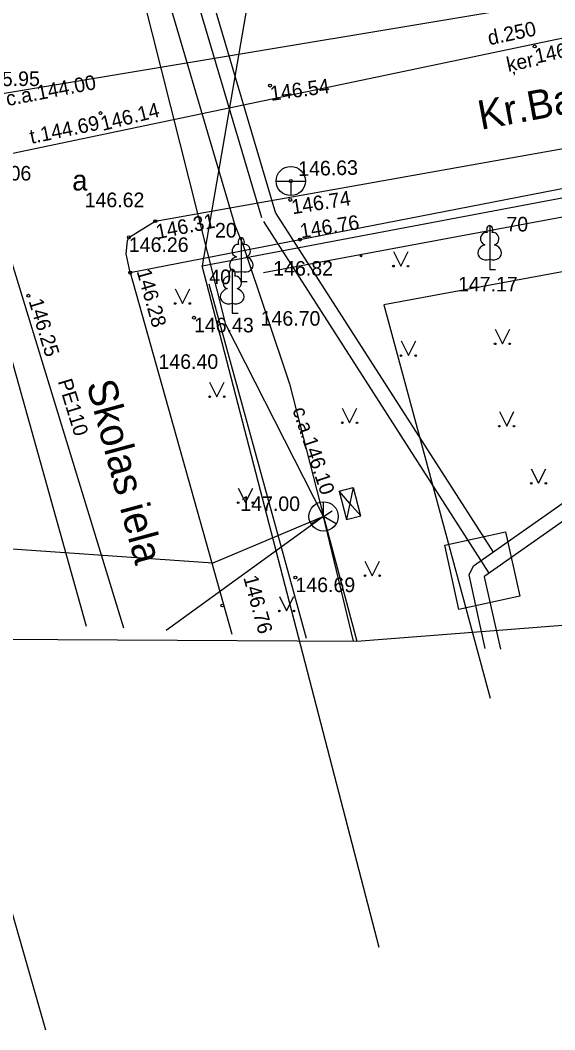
# Model space of a CAD drawing. Extents: x 728492 to 729038, y 272968 to 273171.
# Drawn here: x 728538.74 to 728557.05, y 273019.88 to 273054.47 of the extents above; entities that cross this region are included whole.
import ezdxf

# ---------------------------------------------------------------- set-up
doc = ezdxf.new("R2010")
doc.units = 0
for name, color, linetype in [('APGR_SARK_####_####_#', 7, 'Continuous'), ('CELI_CAPM_####_####_#', 7, 'Continuous'), ('CELI_CMAL_####_####_#', 7, 'Continuous'), ('CELI_CSEG_####_TKST_#', 7, 'Continuous'), ('CELI_IELA_####_TKST_#', 7, 'Continuous'), ('RAMI_UZMR_####_####_#', 7, 'Continuous'), ('RELJ_AATZ_####_TKST_#', 7, 'Continuous'), ('RELJ_ELEM_####_####_#', 7, 'Continuous'), ('ROBZ_UZMR_####_####_#', 7, 'Continuous'), ('SAKK_DETV_####_####_#', 7, 'Continuous'), ('SAKK_ELEM_####_####_#', 7, 'Continuous'), ('SAKK_ELEM_####_TKST_#', 7, 'Continuous'), ('SAKK_KKAN_####_####_#', 7, 'Continuous'), ('SAKK_KKAN_####_TKST_#', 7, 'Continuous'), ('SAKT_ELEM_####_####_#', 7, 'Continuous'), ('SAKT_VADP_KABE_####_#', 7, 'Continuous'), ('SILT_ELEM_####_####_#', 7, 'Continuous'), ('SILT_ELEM_####_TKST_#', 7, 'Continuous'), ('SILT_VADP_UDEN_####_#', 7, 'Continuous'), ('SILT_VADP_UDEN_TKAM_#', 7, 'Continuous'), ('SKAN_ELEM_####_####_#', 7, 'Continuous'), ('SKAN_VADP_PAST_####_#', 7, 'Continuous'), ('SKAN_VADP_PAST_TKST_#', 7, 'Continuous'), ('TERT_DIAM_####_TKST_#', 7, 'Continuous'), ('TERT_DZOG_####_####_#', 7, 'Continuous'), ('TERT_ELEM_####_####_#', 7, 'Continuous'), ('UDTK_ELEM_####_TKST_#', 7, 'Continuous'), ('UDTK_VADP_UDEN_####_#', 7, 'Continuous'), ('UDTK_VADP_UDEN_TKST_#', 7, 'Continuous')]:
    doc.layers.add(name, color=color, linetype=linetype)

msp = doc.modelspace()

# ---------------------------------------------------------------- linework, layer by layer
at = {"layer": 'APGR_SARK_####_####_#'}
for points in [[(728661.295, 273065.109), (728551.197, 273044.726)], [(728551.197, 273044.726), (728554.836, 273031.249)]]:
    msp.add_lwpolyline(points, dxfattribs=at)
at = {"layer": 'CELI_CAPM_####_####_#'}
msp.add_line((728542.512, 273045.823), (728545.993, 273033.435), dxfattribs=at)
for points in [[(728543.367, 273047.586), (728557.526, 273050.114), (728572.173, 273053.046)], [(728542.512, 273045.823), (728542.372, 273046.465), (728542.421, 273046.914), (728542.463, 273047.032), (728543.367, 273047.586)]]:
    msp.add_lwpolyline(points, dxfattribs=at)
at = {"layer": 'CELI_CMAL_####_####_#'}
msp.add_lwpolyline([(728542.512, 273045.823), (728558.294, 273048.902), (728568.705, 273050.681)], dxfattribs=at)
at = {"layer": 'RAMI_UZMR_####_####_#'}
msp.add_lwpolyline([(728545.121, 273067.256), (728525.538, 273066.106), (728511.145, 273059.016), (728527.731, 273033.328), (728550.271, 273033.197), (728572.013, 273034.886), (728580.562, 273045.27), (728653.673, 273058.931), (728671.713, 273053.291), (728688.721, 273058.407), (728702.149, 273066.922)], dxfattribs=at)
at = {"layer": 'RELJ_ELEM_####_####_#'}
for centre in [(728556.357, 273053.573), (728547.298, 273052.233), (728541.493, 273051.291), (728548.006, 273048.962), (728547.989, 273048.314), (728543.367, 273047.586), (728542.463, 273047.032), (728548.324, 273046.957), (728542.512, 273045.823), (728539.025, 273045.032), (728544.694, 273044.277), (728548.167, 273035.378), (728545.667, 273034.42)]:
    msp.add_circle(centre, 0.05, dxfattribs=at)
at = {"layer": 'ROBZ_UZMR_####_####_#'}
for p, q in [((728547.311, 273059.662), (728544.976, 273046.06)), ((728544.976, 273046.06), (728578.327, 273052.35)), ((728551.037, 273022.708), (728544.976, 273046.06)), ((728533.371, 273041.664), (728539.608, 273019.883))]:
    msp.add_line(p, q, dxfattribs=at)
at = {"layer": 'SAKK_DETV_####_####_#'}
msp.add_line((728549.129, 273037.471), (728549.42, 273037.668), dxfattribs=at)
at = {"layer": 'SAKK_ELEM_####_####_#'}
for p, q in [((728549.13, 273037.473), (728549.13, 273037.972)), ((728548.696, 273037.223), (728549.13, 273037.473)), ((728549.13, 273037.473), (728549.129, 273037.472)), ((728549.563, 273037.223), (728549.13, 273037.473))]:
    msp.add_line(p, q, dxfattribs=at)
msp.add_circle((728549.129, 273037.471), 0.5, dxfattribs=at)
at = {"layer": 'SAKK_KKAN_####_####_#'}
msp.add_lwpolyline([(728540.095, 273067.793), (728546.092, 273047.448), (728546.377, 273046.751), (728547.961, 273042.009), (728549.129, 273037.471), (728550.271, 273033.197)], dxfattribs=at)
at = {"layer": 'SAKT_ELEM_####_####_#'}
for p, q in [((728550.146, 273038.464), (728550.399, 273037.493)), ((728549.662, 273038.338), (728549.917, 273037.364))]:
    msp.add_line(p, q, dxfattribs=at)
for points in [[(728550.146, 273038.463), (728550.026, 273037.913), (728549.663, 273038.338)], [(728550.401, 273037.494), (728550.027, 273037.911), (728549.917, 273037.365)]]:
    msp.add_lwpolyline(points, close=True, dxfattribs=at)
at = {"layer": 'SAKT_VADP_KABE_####_#'}
for points in [[(728549.129, 273037.471), (728545.783, 273044.05), (728542.34, 273057.723), (728539.193, 273068.196)], [(728549.129, 273037.471), (728545.341, 273035.871), (728536.823, 273036.463), (728531.461, 273037.656), (728530.594, 273038.125), (728526.6, 273041.809), (728514.8, 273057.81)], [(728549.129, 273037.471), (728543.739, 273033.561)], [(728550.159, 273033.203), (728549.129, 273037.471)]]:
    msp.add_lwpolyline(points, dxfattribs=at)
at = {"layer": 'SILT_ELEM_####_####_#'}
for p, q in [((728547.506, 273048.962), (728548.006, 273048.962)), ((728548.006, 273048.962), (728548.506, 273048.962)), ((728548.006, 273048.962), (728548.006, 273048.462))]:
    msp.add_line(p, q, dxfattribs=at)
msp.add_circle((728548.006, 273048.962), 0.5, dxfattribs=at)
at = {"layer": 'SILT_VADP_UDEN_####_#'}
for p, q in [((728547.012, 273047.706), (728541.056, 273067.855)), ((728547.492, 273047.847), (728541.567, 273067.888))]:
    msp.add_line(p, q, dxfattribs=at)
for points in [[(728554.662, 273032.952), (728554.113, 273035.473), (728554.267, 273035.774), (728581.419, 273054.878), (728582.018, 273055.208), (728610.89, 273060.328), (728630.183, 273063.782), (728638.039, 273065.289), (728652.893, 273068.386), (728653.925, 273076.859), (728654.802, 273077.089)], [(728555.193, 273032.922), (728554.64, 273035.405), (728554.656, 273035.436), (728581.684, 273054.453), (728582.187, 273054.73), (728610.978, 273059.835), (728630.274, 273063.29), (728638.144, 273064.8), (728653.493, 273067.873), (728654.384, 273076.462), (728654.897, 273076.597)], [(728547.492, 273047.847), (728554.932, 273036.242)], [(728547.071, 273047.578), (728554.793, 273035.533)]]:
    msp.add_lwpolyline(points, dxfattribs=at)
at = {"layer": 'SILT_VADP_UDEN_TKAM_#'}
msp.add_lwpolyline([(728553.278, 273036.487), (728555.358, 273036.948), (728555.846, 273034.745), (728553.766, 273034.284)], close=True, dxfattribs=at)
at = {"layer": 'SKAN_VADP_PAST_####_#'}
for points in [[(728536.573, 273049.518), (728565.936, 273055.685), (728568.908, 273039.465), (728569.266, 273036.186)], [(728536.573, 273049.518), (728541, 273033.714)]]:
    msp.add_lwpolyline(points, dxfattribs=at)
at = {"layer": 'TERT_DZOG_####_####_#'}
for points in [[(728547.071, 273045.828), (728573.496, 273050.75)], [(728548.55, 273033.293), (728545.216, 273045.43)]]:
    msp.add_lwpolyline(points, dxfattribs=at)
at = {"layer": 'TERT_ELEM_####_####_#'}
for p, q in [((728551.523, 273046.547), (728551.773, 273046.047)), ((728551.773, 273046.047), (728552.023, 273046.547)), ((728554.817, 273046.281), (728554.817, 273045.934)), ((728546.311, 273045.868), (728546.311, 273045.521)), ((728554.817, 273045.934), (728555.017, 273045.934)), ((728546.311, 273045.521), (728546.511, 273045.521)), ((728544.05, 273045.266), (728544.3, 273044.766)), ((728544.3, 273044.766), (728544.55, 273045.266)), ((728546, 273044.779), (728546, 273044.432)), ((728546, 273044.432), (728546.2, 273044.432)), ((728555.004, 273043.885), (728555.254, 273043.385)), ((728555.254, 273043.385), (728555.504, 273043.885)), ((728551.784, 273043.482), (728552.034, 273042.982)), ((728552.034, 273042.982), (728552.284, 273043.482)), ((728545.229, 273042.072), (728545.479, 273041.572)), ((728545.479, 273041.572), (728545.729, 273042.072)), ((728549.771, 273041.179), (728550.021, 273040.679)), ((728550.021, 273040.679), (728550.271, 273041.179)), ((728555.148, 273041.064), (728555.398, 273040.564)), ((728555.398, 273040.564), (728555.648, 273041.064)), ((728556.24, 273039.107), (728556.49, 273038.607)), ((728556.49, 273038.607), (728556.74, 273039.107)), ((728546.206, 273038.445), (728546.456, 273037.945)), ((728546.456, 273037.945), (728546.706, 273038.445)), ((728550.547, 273035.941), (728550.797, 273035.441)), ((728550.797, 273035.441), (728551.047, 273035.941)), ((728547.615, 273034.733), (728547.865, 273034.233)), ((728547.865, 273034.233), (728548.115, 273034.733))]:
    msp.add_line(p, q, dxfattribs=at)
for points in [[(728554.817, 273047.434), (728554.817, 273046.281)], [(728554.907, 273047.202), (728554.906, 273047.203)], [(728546.311, 273047.021), (728546.311, 273045.868)], [(728546.401, 273046.789), (728546.4, 273046.789)], [(728546, 273045.932), (728546, 273044.779)], [(728546.089, 273045.7), (728546.088, 273045.701)]]:
    msp.add_lwpolyline(points, dxfattribs=at)
for centre, radius in [((728550.408, 273046.397), 0.028), ((728551.523, 273046.046), 0.028), ((728552.023, 273046.046), 0.0263), ((728544.05, 273044.766), 0.028), ((728544.55, 273044.766), 0.0263), ((728555.003, 273043.384), 0.028), ((728555.503, 273043.384), 0.0263), ((728551.783, 273042.981), 0.028), ((728552.283, 273042.981), 0.0263), ((728545.228, 273041.571), 0.028), ((728545.728, 273041.571), 0.0263), ((728549.771, 273040.679), 0.028), ((728550.271, 273040.679), 0.0263), ((728555.147, 273040.564), 0.028), ((728555.647, 273040.564), 0.0263), ((728556.24, 273038.607), 0.028), ((728556.74, 273038.607), 0.0263), ((728546.206, 273037.945), 0.028), ((728546.706, 273037.945), 0.0263), ((728550.547, 273035.441), 0.028), ((728551.047, 273035.441), 0.0263), ((728547.615, 273034.232), 0.028), ((728548.115, 273034.232), 0.0263)]:
    msp.add_circle(centre, radius, dxfattribs=at)
for centre, major_axis, ratio, start_param, end_param in [((728554.817, 273047.284), (0, -0.15), 0.707107, 3.14537, 5.287485), ((728554.817, 273047.284), (0, -0.15), 0.707107, 0.995701, 3.137816), ((728554.689, 273046.989), (-0.039, -0.212), 0.861323, 3.141593, 6.283185), ((728554.945, 273046.989), (0.039, -0.212), 0.861323, 0, 3.141593), ((728546.183, 273046.576), (-0.039, -0.212), 0.861323, 3.141593, 6.283185), ((728546.311, 273046.871), (0, -0.15), 0.707107, 3.14537, 5.287485), ((728546.311, 273046.871), (0, -0.15), 0.707107, 0.995701, 3.137816), ((728546.439, 273046.576), (0.039, -0.212), 0.861323, 0, 3.141593), ((728554.727, 273046.527), (0.307, 0.095), 0.814445, 1.570796, 4.752015), ((728554.907, 273046.527), (-0.307, 0.095), 0.814445, 1.531171, 4.712389), ((728546.221, 273046.114), (0.307, 0.095), 0.814445, 1.570796, 4.752015), ((728546.401, 273046.114), (-0.307, 0.095), 0.814445, 1.531171, 4.712389), ((728545.871, 273045.488), (-0.039, -0.212), 0.861323, 3.141593, 6.283185), ((728546, 273045.782), (0, -0.15), 0.707107, 3.14537, 5.287485), ((728545.999, 273045.782), (0, -0.15), 0.707107, 0.995701, 3.137816), ((728546.128, 273045.488), (0.039, -0.212), 0.861323, 0, 3.141593), ((728545.91, 273045.025), (0.307, 0.095), 0.814445, 1.570796, 4.752015), ((728546.089, 273045.025), (-0.307, 0.095), 0.814445, 1.531171, 4.712389)]:
    msp.add_ellipse(centre, major_axis=major_axis, ratio=ratio, start_param=start_param, end_param=end_param, dxfattribs=at)
at = {"layer": 'UDTK_VADP_UDEN_####_#'}
msp.add_line((728542.296, 273033.642), (728536.753, 273051.73), dxfattribs=at)
msp.add_lwpolyline([(728536.753, 273051.73), (728562.041, 273055.954), (728585.763, 273058.374), (728605.397, 273061.619), (728606.945, 273061.767), (728607.469, 273061.897), (728613.688, 273063.022), (728614.11, 273063.005), (728657.437, 273069.243)], dxfattribs=at)

# ---------------------------------------------------------------- texts
at = {"layer": 'CELI_CSEG_####_TKST_#'}
msp.add_text('a', height=0.7, dxfattribs=at).set_placement((728540.524, 273048.638))
at = {"layer": 'CELI_IELA_####_TKST_#'}
for s, rotation, p in [('Kr.Barona iela', 10.511, (728554.514, 273050.714)), ('Skolas iela', 285.14, (728541.005, 273042.012))]:
    msp.add_text(s, height=1, rotation=rotation, dxfattribs=at).set_placement(p)
at = {"layer": 'RELJ_AATZ_####_TKST_#'}
for s, rotation, p in [('146.80', 11.9537, (728556.419, 273052.986)), ('146.54', 7.6691, (728547.333, 273051.707)), ('146.14', 14.1646, (728541.567, 273050.675)), ('146.74', 8.9799, (728548.067, 273047.82)), ('146.31', 11.319, (728543.442, 273046.969)), ('146.76', 8.9799, (728548.36, 273046.997)), ('146.28', 285.847, (728542.725, 273045.873)), ('146.25', 287.0578, (728539.025, 273044.854)), ('146.76', 285.2431, (728546.378, 273035.38))]:
    msp.add_text(s, height=0.5, rotation=rotation, dxfattribs=at).set_placement(p)
for s, p in [(' 146.62', (728540.764, 273048.066)), ('146.26', (728542.463, 273046.532)), (' 146.82', (728547.221, 273045.72)), (' 147.17', (728553.545, 273045.179)), (' 146.70', (728546.789, 273044.006)), ('146.43', (728544.694, 273043.777)), (' 146.40', (728543.291, 273042.526)), ('146.69', (728548.167, 273034.878))]:
    msp.add_text(s, height=0.5, dxfattribs=at).set_placement(p)
at = {"layer": 'SAKK_ELEM_####_TKST_#'}
msp.add_text(' 147.00', height=0.5, dxfattribs=at).set_placement((728546.093, 273037.657))
at = {"layer": 'SAKK_KKAN_####_TKST_#'}
msp.add_text('c.a.146.10', height=0.5, rotation=288.6132, dxfattribs=at).set_placement((728548.056, 273041.126))
at = {"layer": 'SILT_ELEM_####_TKST_#'}
msp.add_text('146.63', height=0.5, rotation=1.24, dxfattribs=at).set_placement((728548.265, 273049.134))
at = {"layer": 'SKAN_ELEM_####_####_#'}
msp.add_text('146.06', height=0.5, dxfattribs=at).set_placement((728537.078, 273048.979))
at = {"layer": 'SKAN_VADP_PAST_TKST_#'}
for s, p in [('d.250', (728554.805, 273053.612)), ('ķer.', (728555.451, 273052.7)), ('t.144.69', (728539.125, 273050.231))]:
    msp.add_text(s, height=0.5, rotation=11.861, dxfattribs=at).set_placement(p)
at = {"layer": 'TERT_DIAM_####_TKST_#'}
for s, p in [('20', (728545.411, 273047.025)), ('70', (728555.389, 273047.233)), ('40', (728545.216, 273045.43))]:
    msp.add_text(s, height=0.5, dxfattribs=at).set_placement(p)
at = {"layer": 'UDTK_ELEM_####_TKST_#'}
msp.add_text('145.95', height=0.5, dxfattribs=at).set_placement((728537.371, 273052.216))
at = {"layer": 'UDTK_VADP_UDEN_TKST_#'}
for s, rotation, p in [('c.a.144.00', 10.8909, (728538.306, 273051.527)), ('PE110', 287.039, (728540.025, 273042.101))]:
    msp.add_text(s, height=0.5, rotation=rotation, dxfattribs=at).set_placement(p)

doc.saveas('drawing.dxf')
